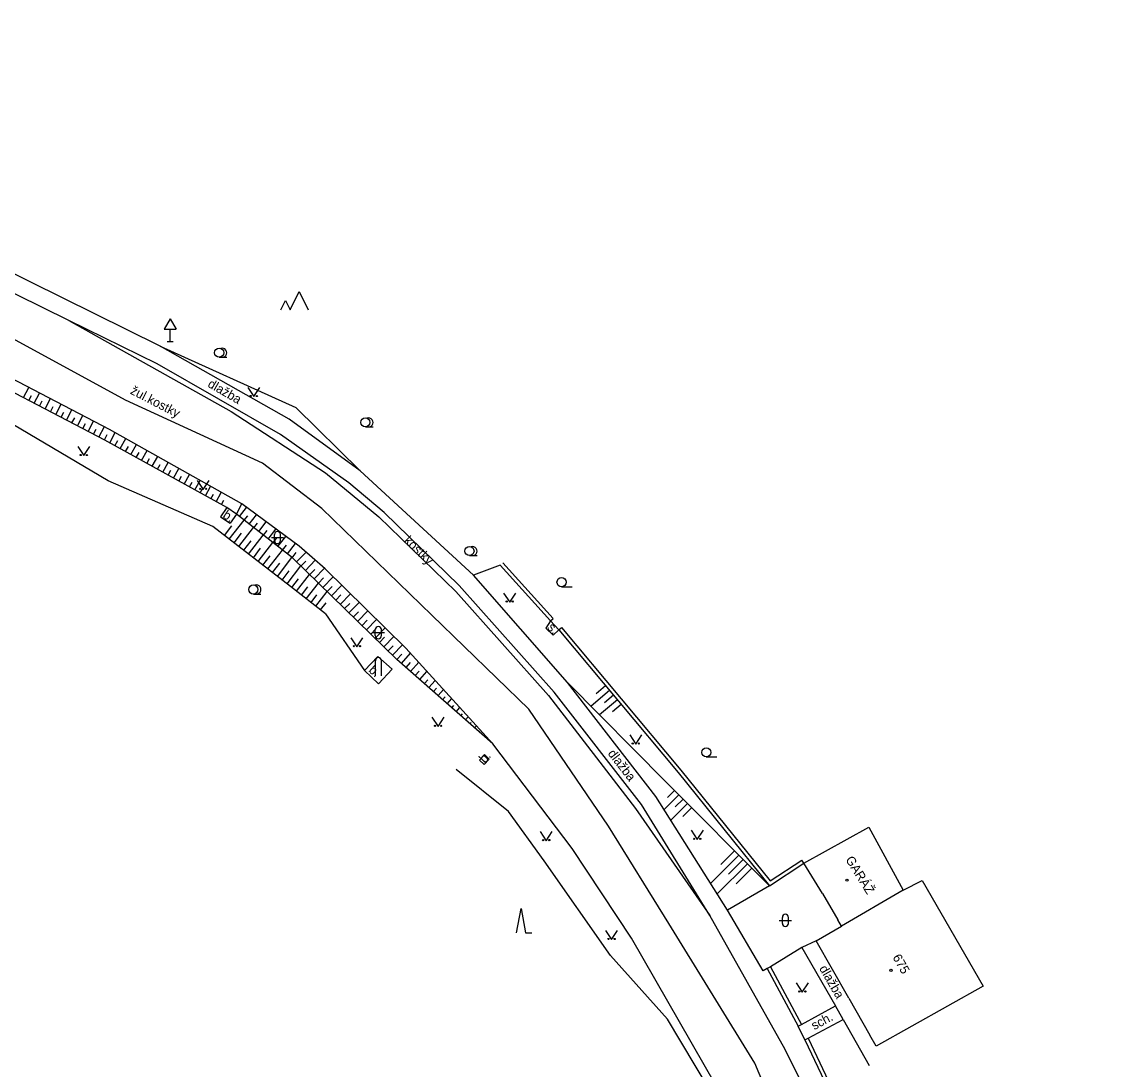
# Model space of a CAD drawing. Extents: x -621516 to -621304, y -1175233 to -1174899.
# Drawn here: x -621425.3 to -621334.6, y -1175077 to -1174990.9 of the extents above; entities that cross this region are included whole.
import ezdxf

# ---------------------------------------------------------------- set-up
doc = ezdxf.new("R2010")
doc.units = 0
for name, color, linetype in [('Budovy - měřené', 7, 'Continuous'), ('Budovy - zadní trakty', 7, 'Continuous'), ('Doplňkové značky', 7, 'Continuous'), ('Pomocné popisy', 7, 'Continuous'), ('Rozhraní ploch', 7, 'Continuous'), ('Výškopis', 7, 'Continuous'), ('Zeleň', 7, 'Continuous'), ('Značky druhů budov', 7, 'Continuous'), ('Značky kultur', 7, 'Continuous'), ('Čísla popisná_evidenční', 7, 'Continuous')]:
    doc.layers.add(name, color=color, linetype=linetype)

msp = doc.modelspace()

# ---------------------------------------------------------------- linework, layer by layer
at = {"layer": 'Budovy - měřené'}
for p, q in [((-621359.47, -1175062.5), (-621361.01, -1175060.02)), ((-621357.9, -1175065.19), (-621358.2, -1175064.67)), ((-621355.06, -1175075.06), (-621355.59, -1175074.13))]:
    msp.add_line(p, q, dxfattribs=at)
msp.add_lwpolyline([(-621357.3, -1175071.09), (-621359.98, -1175066.39), (-621357.9, -1175065.19)], dxfattribs=at)
at = {"layer": 'Budovy - zadní trakty'}
for points in [[(-621361.01, -1175060.02), (-621355.66, -1175057.04), (-621352.83, -1175062.22), (-621357.9, -1175065.19)], [(-621352.83, -1175062.22), (-621351.28, -1175061.43), (-621346.27, -1175070.12), (-621355.06, -1175075.06)]]:
    msp.add_lwpolyline(points, dxfattribs=at)
at = {"layer": 'Doplňkové značky'}
for p, q in [((-621413.09, -1175015.274), (-621413.59, -1175016.14)), ((-621413.09, -1175015.274), (-621412.59, -1175016.14)), ((-621413.59, -1175016.14), (-621412.59, -1175016.14)), ((-621413.09, -1175017.14), (-621413.09, -1175016.14)), ((-621413.34, -1175017.14), (-621412.84, -1175017.14)), ((-621385.97, -1175035.52), (-621381.83, -1175040.09)), ((-621385.75, -1175035.32), (-621381.61, -1175039.89)), ((-621381.83, -1175040.09), (-621382.21, -1175040.69)), ((-621381.83, -1175040.09), (-621381.61, -1175039.89)), ((-621381.15, -1175040.84), (-621381.83, -1175040.09)), ((-621382.21, -1175040.69), (-621381.61, -1175041.26)), ((-621381.61, -1175041.26), (-621381.15, -1175040.84)), ((-621381.15, -1175040.84), (-621380.92, -1175040.65)), ((-621396.22, -1175044.62), (-621396.22, -1175043.37)), ((-621395.72, -1175044.62), (-621395.72, -1175043.37)), ((-621361.01, -1175060.02), (-621361.17, -1175059.77)), ((-621359.47, -1175062.5), (-621358.2, -1175064.67)), ((-621364.01, -1175068.66), (-621361.46, -1175073.4)), ((-621363.75, -1175068.52), (-621361.2, -1175073.26)), ((-621357.3, -1175071.09), (-621355.59, -1175074.13)), ((-621361.2, -1175073.26), (-621358.4, -1175071.72)), ((-621357.76, -1175072.85), (-621358.4, -1175071.72)), ((-621360.66, -1175074.39), (-621357.76, -1175072.85)), ((-621361.46, -1175073.4), (-621361.2, -1175073.26)), ((-621360.93, -1175074.52), (-621361.46, -1175073.4)), ((-621360.93, -1175074.52), (-621360.66, -1175074.39))]:
    msp.add_line(p, q, dxfattribs=at)
for points in [[(-621403.99, -1175014.53), (-621403.615, -1175013.78), (-621403.24, -1175014.53), (-621402.49, -1175013.03), (-621401.74, -1175014.53)], [(-621381.15, -1175040.84), (-621371.34, -1175052.55), (-621363.84, -1175061.86), (-621361.01, -1175060.02)], [(-621380.92, -1175040.65), (-621371.108, -1175052.36), (-621363.776, -1175061.461), (-621361.17, -1175059.77)], [(-621361.16, -1175066.94), (-621363.75, -1175068.52), (-621364.01, -1175068.66)], [(-621360.93, -1175074.52), (-621358.25, -1175080.16), (-621354.38, -1175088.33), (-621352.15, -1175086.92)], [(-621360.66, -1175074.39), (-621354.254, -1175087.895), (-621352.31, -1175086.67)]]:
    msp.add_lwpolyline(points, dxfattribs=at)
msp.add_arc((-621395.97, -1175043.37), 0.25, 0, 179.99999, dxfattribs=at)
at = {"layer": 'Rozhraní ploch'}
for p, q in [((-621413.91, -1175017.52), (-621427.27, -1175010.93)), ((-621408.44, -1175030.79), (-621408.95, -1175031.54)), ((-621407.64, -1175031.33), (-621408.44, -1175030.79)), ((-621407.64, -1175031.33), (-621408.15, -1175032.08)), ((-621408.95, -1175031.54), (-621408.15, -1175032.08)), ((-621396.03, -1175043.02), (-621397.12, -1175044.18)), ((-621396.03, -1175043.02), (-621394.84, -1175044.08)), ((-621397.12, -1175044.18), (-621395.96, -1175045.27)), ((-621394.84, -1175044.08), (-621395.96, -1175045.27)), ((-621387.25, -1175051.09), (-621387.67, -1175051.54)), ((-621387.25, -1175051.09), (-621386.87, -1175051.47)), ((-621387.67, -1175051.54), (-621387.28, -1175051.91)), ((-621386.87, -1175051.47), (-621387.28, -1175051.91)), ((-621362.53, -1175075.31), (-621368.73, -1175064.3)), ((-621357.76, -1175072.85), (-621355.63, -1175076.64))]:
    msp.add_line(p, q, dxfattribs=at)
for points in [[(-621421.41, -1175015.41), (-621427.83, -1175012.26), (-621432.62, -1175009.84), (-621442.92, -1175004.13), (-621451.63, -1174998.17), (-621460.93, -1174990.89)], [(-621334.61, -1175169.74), (-621337.93, -1175156.21), (-621341.04, -1175144), (-621345.71, -1175128.29), (-621348.52, -1175118.58), (-621351.83, -1175109.02), (-621355.96, -1175097.53), (-621358.67, -1175090.23), (-621362.68, -1175082.07), (-621365.02, -1175076.44), (-621372.11, -1175064.96), (-621377.05, -1175056.97), (-621383.6, -1175047.36), (-621391.59, -1175039.63), (-621400.61, -1175030.85), (-621405.51, -1175027.13), (-621416.77, -1175021.96), (-621429.4, -1175015.08)], [(-621368.73, -1175064.3), (-621374.36, -1175055.2), (-621381.54, -1175045.95), (-621389.33, -1175037.18), (-621395.5, -1175031.18), (-621398.41, -1175028.76), (-621404.01, -1175024.79), (-621414.15, -1175018.97), (-621421.41, -1175015.41)], [(-621421.41, -1175015.41), (-621408.08, -1175022.9), (-621400.31, -1175027.93), (-621395.93, -1175031.56), (-621389.62, -1175037.68), (-621381.99, -1175046.24), (-621374.83, -1175055.51), (-621368.73, -1175064.3)], [(-621361.69, -1175091.69), (-621365.44, -1175083.96), (-621368.23, -1175078.24), (-621375.16, -1175066.17), (-621380.05, -1175058.81), (-621386.57, -1175050.21), (-621393.72, -1175042.33), (-621400.36, -1175035.83), (-621402.49, -1175033.96), (-621407.21, -1175030.49), (-621418.07, -1175024.36), (-621430.6, -1175017.86)], [(-621397.48, -1175027.77), (-621403.31, -1175023.51), (-621413.91, -1175017.52)], [(-621380.42, -1175045.15), (-621388.17, -1175036.35), (-621397.48, -1175027.77)], [(-621367.28, -1175063.87), (-621373.16, -1175054.53), (-621380.42, -1175045.15)], [(-621364.01, -1175068.66), (-621364.34, -1175068.86), (-621367.28, -1175063.87)], [(-621359.98, -1175066.39), (-621361.16, -1175066.94), (-621358.4, -1175071.72)], [(-621356.03, -1175088.91), (-621359.75, -1175080.94), (-621362.53, -1175075.31)]]:
    msp.add_lwpolyline(points, dxfattribs=at)
at = {"layer": 'Výškopis'}
for p, q in [((-621425.152, -1175021.754), (-621424.714, -1175020.913)), ((-621424.265, -1175022.216), (-621423.827, -1175021.374)), ((-621424.709, -1175021.985), (-621424.49, -1175021.564)), ((-621423.822, -1175022.447), (-621423.602, -1175022.026)), ((-621423.378, -1175022.678), (-621422.939, -1175021.834)), ((-621422.492, -1175023.14), (-621422.051, -1175022.295)), ((-621422.935, -1175022.909), (-621422.715, -1175022.487)), ((-621422.048, -1175023.371), (-621421.828, -1175022.948)), ((-621421.605, -1175023.602), (-621421.164, -1175022.755)), ((-621420.718, -1175024.064), (-621420.276, -1175023.216)), ((-621421.161, -1175023.833), (-621420.94, -1175023.409)), ((-621420.274, -1175024.295), (-621420.053, -1175023.87)), ((-621419.831, -1175024.526), (-621419.388, -1175023.676)), ((-621418.944, -1175024.988), (-621418.501, -1175024.137)), ((-621419.387, -1175024.757), (-621419.166, -1175024.332)), ((-621418.5, -1175025.219), (-621418.279, -1175024.793)), ((-621418.063, -1175025.46), (-621417.6, -1175024.625)), ((-621417.188, -1175025.945), (-621416.729, -1175025.117)), ((-621417.625, -1175025.702), (-621417.395, -1175025.287)), ((-621416.75, -1175026.187), (-621416.522, -1175025.775)), ((-621416.313, -1175026.429), (-621415.858, -1175025.608)), ((-621415.876, -1175026.671), (-621415.649, -1175026.263)), ((-621415.438, -1175026.914), (-621414.987, -1175026.1)), ((-621415.001, -1175027.156), (-621414.776, -1175026.751)), ((-621414.563, -1175027.398), (-621414.117, -1175026.592)), ((-621414.126, -1175027.641), (-621413.904, -1175027.239)), ((-621413.689, -1175027.883), (-621413.246, -1175027.083)), ((-621413.251, -1175028.125), (-621413.031, -1175027.727)), ((-621412.814, -1175028.367), (-621412.375, -1175027.575)), ((-621412.376, -1175028.61), (-621412.158, -1175028.215)), ((-621411.939, -1175028.852), (-621411.504, -1175028.066)), ((-621411.502, -1175029.094), (-621411.285, -1175028.703)), ((-621411.064, -1175029.336), (-621410.633, -1175028.558)), ((-621410.627, -1175029.579), (-621410.412, -1175029.191)), ((-621410.19, -1175029.821), (-621409.762, -1175029.049)), ((-621409.752, -1175030.063), (-621409.539, -1175029.679)), ((-621409.315, -1175030.305), (-621408.891, -1175029.541)), ((-621408.877, -1175030.548), (-621408.667, -1175030.167)), ((-621407.392, -1175031.524), (-621406.813, -1175030.782)), ((-621406.998, -1175031.832), (-621406.704, -1175031.455)), ((-621406.604, -1175032.139), (-621406.007, -1175031.375)), ((-621408.627, -1175033.075), (-621408.02, -1175032.291)), ((-621408.231, -1175033.381), (-621407.02, -1175031.814)), ((-621406.21, -1175032.447), (-621405.907, -1175032.059)), ((-621405.815, -1175032.755), (-621405.201, -1175031.967)), ((-621407.836, -1175033.687), (-621407.231, -1175032.904)), ((-621407.44, -1175033.993), (-621406.232, -1175032.43)), ((-621406.649, -1175034.604), (-621405.444, -1175033.045)), ((-621405.421, -1175033.063), (-621405.109, -1175032.663)), ((-621405.027, -1175033.37), (-621404.394, -1175032.56)), ((-621404.633, -1175033.678), (-621404.312, -1175033.267)), ((-621404.239, -1175033.986), (-621403.588, -1175033.152)), ((-621407.045, -1175034.298), (-621406.441, -1175033.518)), ((-621406.254, -1175034.91), (-621405.652, -1175034.132)), ((-621405.858, -1175035.216), (-621404.655, -1175033.661)), ((-621403.845, -1175034.293), (-621403.515, -1175033.871)), ((-621403.451, -1175034.601), (-621402.782, -1175033.745)), ((-621405.463, -1175035.522), (-621404.862, -1175034.745)), ((-621405.067, -1175035.828), (-621403.867, -1175034.276)), ((-621404.276, -1175036.44), (-621403.079, -1175034.892)), ((-621403.057, -1175034.909), (-621402.722, -1175034.48)), ((-621402.696, -1175035.255), (-621401.922, -1175034.459)), ((-621401.979, -1175035.952), (-621401.17, -1175035.119)), ((-621404.672, -1175036.134), (-621404.072, -1175035.359)), ((-621403.881, -1175036.746), (-621403.297, -1175035.991)), ((-621403.485, -1175037.052), (-621402.353, -1175035.588)), ((-621402.337, -1175035.603), (-621401.942, -1175035.196)), ((-621401.62, -1175036.3), (-621401.207, -1175035.875)), ((-621401.262, -1175036.649), (-621400.417, -1175035.78)), ((-621403.09, -1175037.358), (-621402.539, -1175036.651)), ((-621402.696, -1175037.665), (-621401.627, -1175036.294)), ((-621400.903, -1175036.997), (-621400.48, -1175036.562)), ((-621400.545, -1175037.346), (-621399.7, -1175036.476)), ((-621402.302, -1175037.973), (-621401.784, -1175037.309)), ((-621401.907, -1175038.28), (-621400.905, -1175036.995)), ((-621401.119, -1175038.895), (-621400.184, -1175037.696)), ((-621400.186, -1175037.694), (-621399.764, -1175037.26)), ((-621399.828, -1175038.043), (-621398.985, -1175037.176)), ((-621401.513, -1175038.588), (-621401.029, -1175037.967)), ((-621400.724, -1175039.203), (-621400.274, -1175038.625)), ((-621399.469, -1175038.391), (-621399.049, -1175037.958)), ((-621399.111, -1175038.74), (-621398.271, -1175037.875)), ((-621398.752, -1175039.088), (-621398.333, -1175038.657)), ((-621398.394, -1175039.437), (-621397.556, -1175038.575)), ((-621400.33, -1175039.51), (-621397.12, -1175044.18)), ((-621398.035, -1175039.785), (-621397.617, -1175039.355)), ((-621397.677, -1175040.134), (-621396.841, -1175039.274)), ((-621397.318, -1175040.482), (-621396.901, -1175040.053)), ((-621396.959, -1175040.831), (-621396.127, -1175039.974)), ((-621396.601, -1175041.179), (-621396.185, -1175040.752)), ((-621396.242, -1175041.528), (-621395.412, -1175040.674)), ((-621395.884, -1175041.876), (-621395.469, -1175041.45)), ((-621395.525, -1175042.225), (-621394.698, -1175041.373)), ((-621395.167, -1175042.573), (-621394.753, -1175042.148)), ((-621394.808, -1175042.922), (-621393.983, -1175042.073)), ((-621394.45, -1175043.27), (-621394.06, -1175042.828)), ((-621394.074, -1175043.601), (-621393.332, -1175042.758)), ((-621393.699, -1175043.931), (-621393.347, -1175043.531)), ((-621393.324, -1175044.262), (-621392.656, -1175043.503)), ((-621392.949, -1175044.592), (-621392.633, -1175044.234)), ((-621392.574, -1175044.923), (-621391.98, -1175044.248)), ((-621392.198, -1175045.253), (-621391.92, -1175044.937)), ((-621391.823, -1175045.584), (-621391.303, -1175044.993)), ((-621391.448, -1175045.914), (-621391.207, -1175045.64)), ((-621391.073, -1175046.244), (-621390.627, -1175045.739)), ((-621376.976, -1175045.823), (-621378.498, -1175047.098)), ((-621377.297, -1175045.439), (-621378.074, -1175046.09)), ((-621390.697, -1175046.575), (-621390.493, -1175046.343)), ((-621390.322, -1175046.905), (-621389.951, -1175046.484)), ((-621376.334, -1175046.589), (-621377.794, -1175047.812)), ((-621376.655, -1175046.206), (-621377.4, -1175046.83)), ((-621389.947, -1175047.236), (-621389.78, -1175047.046)), ((-621389.572, -1175047.566), (-621389.275, -1175047.229)), ((-621389.197, -1175047.897), (-621389.067, -1175047.749)), ((-621376.013, -1175046.972), (-621376.727, -1175047.571)), ((-621388.821, -1175048.227), (-621388.599, -1175047.974)), ((-621388.446, -1175048.558), (-621388.353, -1175048.452)), ((-621388.071, -1175048.888), (-621387.922, -1175048.72)), ((-621387.696, -1175049.219), (-621387.64, -1175049.155)), ((-621387.32, -1175049.549), (-621387.246, -1175049.465)), ((-621371.637, -1175054.044), (-621372.199, -1175054.605)), ((-621371.284, -1175054.398), (-621372.487, -1175055.599)), ((-621370.931, -1175054.752), (-621371.572, -1175055.392)), ((-621370.578, -1175055.106), (-621371.941, -1175056.466)), ((-621370.225, -1175055.46), (-621370.946, -1175056.18)), ((-621366.34, -1175059.354), (-621368.664, -1175061.672)), ((-621366.693, -1175059), (-621367.815, -1175060.119)), ((-621365.634, -1175060.062), (-621368.117, -1175062.54)), ((-621365.987, -1175059.708), (-621367.189, -1175060.907)), ((-621365.281, -1175060.416), (-621366.563, -1175061.695))]:
    msp.add_line(p, q, dxfattribs=at)
for points in [[(-621408.44, -1175030.79), (-621418.46, -1175025.24), (-621431.4, -1175018.5), (-621436.44, -1175015.82), (-621446.79, -1175010.49)], [(-621400.33, -1175039.51), (-621403.19, -1175037.28), (-621409.59, -1175032.33), (-621418.2, -1175028.58), (-621431.22, -1175020.88)], [(-621386.57, -1175050.21), (-621394.45, -1175043.27), (-621403.03, -1175034.93), (-621407.64, -1175031.33)], [(-621380.42, -1175045.15), (-621372.36, -1175053.32), (-621363.84, -1175061.86)]]:
    msp.add_lwpolyline(points, dxfattribs=at)
at = {"layer": 'Zeleň'}
for p, q in [((-621407.64, -1175031.33), (-621407.21, -1175030.49)), ((-621385.97, -1175035.52), (-621388.17, -1175036.35)), ((-621363.84, -1175061.86), (-621367.28, -1175063.87))]:
    msp.add_line(p, q, dxfattribs=at)
for points in [[(-621413.91, -1175017.52), (-621402.76, -1175022.57), (-621397.48, -1175027.77)], [(-621362.35, -1175091.94), (-621365.78, -1175084.29), (-621368.75, -1175078.62), (-621372.2, -1175072.82), (-621376.9, -1175067.6), (-621382.35, -1175059.81), (-621385.28, -1175055.75), (-621389.58, -1175052.31)]]:
    msp.add_lwpolyline(points, dxfattribs=at)
at = {"layer": 'Značky druhů budov'}
for centre in [(-621357.46, -1175061.41), (-621353.84, -1175068.82)]:
    msp.add_circle(centre, 0.0875, dxfattribs=at)
at = {"layer": 'Značky kultur'}
for p, q in [((-621409.06, -1175018.435), (-621408.435, -1175018.435)), ((-621397.04, -1175024.165), (-621396.415, -1175024.165)), ((-621404.77, -1175033.25), (-621403.77, -1175033.25)), ((-621404.52, -1175033.5), (-621404.52, -1175033)), ((-621404.02, -1175033.5), (-621404.02, -1175033)), ((-621388.49, -1175034.735), (-621387.865, -1175034.735)), ((-621380.92, -1175037.295), (-621380.045, -1175037.295)), ((-621406.25, -1175037.895), (-621405.625, -1175037.895)), ((-621396.48, -1175041.06), (-621395.48, -1175041.06)), ((-621396.23, -1175041.31), (-621396.23, -1175040.81)), ((-621395.73, -1175041.31), (-621395.73, -1175040.81)), ((-621369.024, -1175051.284), (-621368.149, -1175051.284)), ((-621363.02, -1175064.71), (-621362.02, -1175064.71)), ((-621362.77, -1175064.96), (-621362.77, -1175064.46)), ((-621362.27, -1175064.96), (-621362.27, -1175064.46))]:
    msp.add_line(p, q, dxfattribs=at)
for points in [[(-621406.72, -1175020.92), (-621406.22, -1175021.67), (-621405.72, -1175020.92)], [(-621420.69, -1175025.77), (-621420.19, -1175026.52), (-621419.69, -1175025.77)], [(-621410.88, -1175028.55), (-621410.38, -1175029.3), (-621409.88, -1175028.55)], [(-621385.68, -1175037.81), (-621385.18, -1175038.56), (-621384.68, -1175037.81)], [(-621398.24, -1175041.48), (-621397.74, -1175042.23), (-621397.24, -1175041.48)], [(-621391.57, -1175048.02), (-621391.07, -1175048.77), (-621390.57, -1175048.02)], [(-621375.32, -1175049.47), (-621374.82, -1175050.22), (-621374.32, -1175049.47)], [(-621382.68, -1175057.41), (-621382.18, -1175058.16), (-621381.68, -1175057.41)], [(-621370.264, -1175057.309), (-621369.764, -1175058.059), (-621369.264, -1175057.309)], [(-621384.625, -1175065.74), (-621384.25, -1175063.74), (-621383.875, -1175065.74), (-621383.375, -1175065.74)], [(-621377.31, -1175065.54), (-621376.81, -1175066.29), (-621376.31, -1175065.54)], [(-621361.63, -1175069.85), (-621361.13, -1175070.6), (-621360.63, -1175069.85)]]:
    msp.add_lwpolyline(points, dxfattribs=at)
for centre, radius in [((-621409.06, -1175018.06), 0.375), ((-621406.47, -1175021.62), 0.05), ((-621405.97, -1175021.62), 0.05), ((-621397.04, -1175023.79), 0.375), ((-621420.44, -1175026.47), 0.05), ((-621419.94, -1175026.47), 0.05), ((-621410.63, -1175029.25), 0.05), ((-621410.13, -1175029.25), 0.05), ((-621388.49, -1175034.36), 0.375), ((-621380.92, -1175036.92), 0.375), ((-621406.25, -1175037.52), 0.375), ((-621385.43, -1175038.51), 0.05), ((-621384.93, -1175038.51), 0.05), ((-621397.99, -1175042.18), 0.05), ((-621397.49, -1175042.18), 0.05), ((-621391.32, -1175048.72), 0.05), ((-621390.82, -1175048.72), 0.05), ((-621375.07, -1175050.17), 0.05), ((-621374.57, -1175050.17), 0.05), ((-621369.024, -1175050.909), 0.375), ((-621382.43, -1175058.11), 0.05), ((-621381.93, -1175058.11), 0.05), ((-621370.014, -1175058.009), 0.05), ((-621369.514, -1175058.009), 0.05), ((-621377.06, -1175066.24), 0.05), ((-621376.56, -1175066.24), 0.05), ((-621361.38, -1175070.55), 0.05), ((-621360.88, -1175070.55), 0.05)]:
    msp.add_circle(centre, radius, dxfattribs=at)
for centre, radius, start, end in [((-621408.81, -1175018.06), 0.375, 249.49437, 109.04743), ((-621396.79, -1175023.79), 0.375, 249.49437, 109.04743), ((-621404.27, -1175033), 0.25, 0, 179.99999), ((-621404.27, -1175033.5), 0.25, 179.99999, 359.99999), ((-621388.24, -1175034.36), 0.375, 249.49437, 109.04743), ((-621406, -1175037.52), 0.375, 249.49437, 109.04743), ((-621395.98, -1175040.81), 0.25, 0, 179.99999), ((-621395.98, -1175041.31), 0.25, 179.99999, 359.99999), ((-621362.52, -1175064.46), 0.25, 0, 179.99999), ((-621362.52, -1175064.96), 0.25, 179.99999, 359.99999)]:
    msp.add_arc(centre, radius, start, end, dxfattribs=at)

# ---------------------------------------------------------------- texts
at = {"layer": 'Pomocné popisy'}
for s, rotation, p in [('dlažba', 330.15, (-621410.07, -1175020.83)), ('žul.kostky', 332.58, (-621416.428, -1175021.401)), ('b.', 325.98, (-621408.83, -1175031.56)), ('kostky', 315.87573, (-621393.93, -1175033.57)), ('s.', 316.4688, (-621382.14, -1175040.71)), ('b.', 318.30675, (-621396.84, -1175044.23)), ('b.', 47.02, (-621387.24, -1175051.84)), ('dlažba', 307.82, (-621377.16, -1175051.01)), ('GARÁŽ', 301.84, (-621357.61, -1175059.71)), ('dlažba', 300.00239, (-621359.77, -1175068.66)), ('sch.', 27.96984, (-621360.15, -1175073.74))]:
    msp.add_text(s, height=0.75, rotation=rotation, dxfattribs=at).set_placement(p)
at = {"layer": 'Čísla popisná_evidenční'}
msp.add_text('675', height=0.75, rotation=299.69, dxfattribs=at).set_placement((-621353.737, -1175067.742))

doc.saveas('drawing.dxf')
